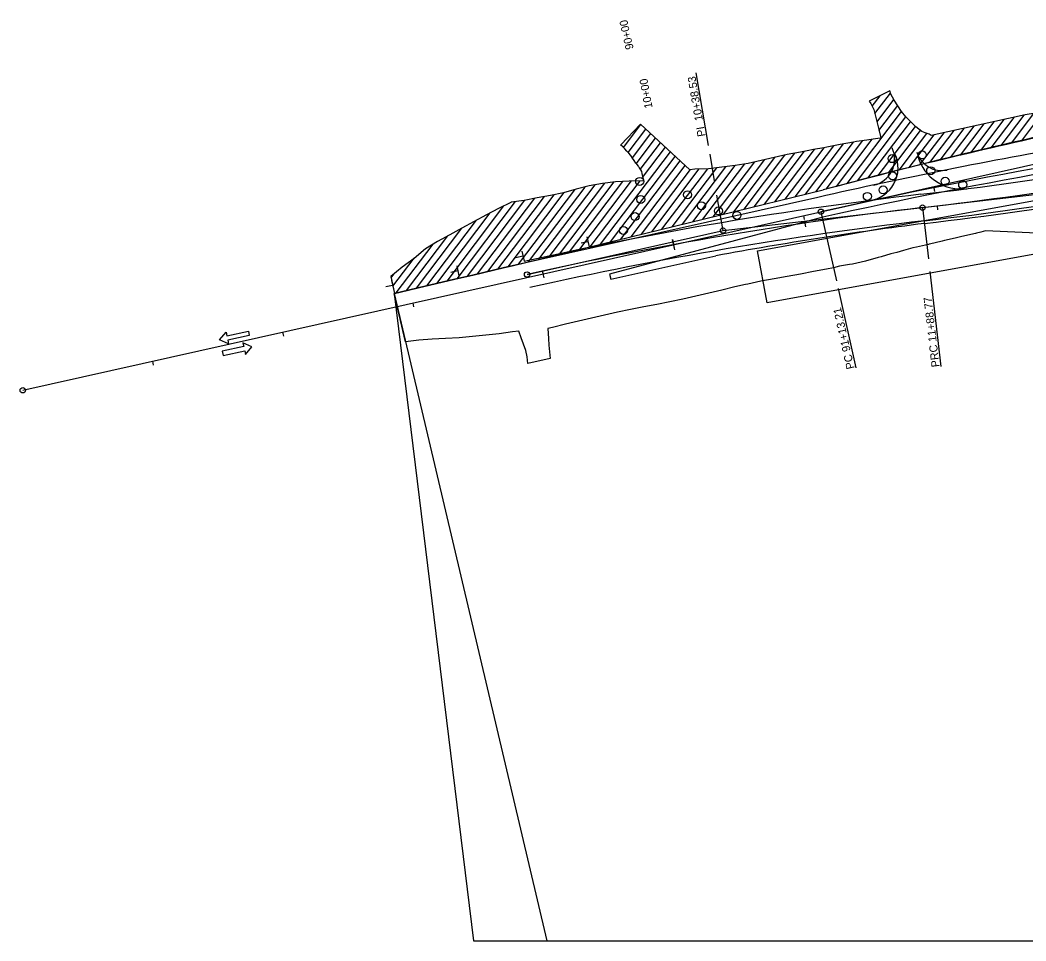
# Model space of a CAD drawing. Extents: x 1568809 to 1572786, y 728326 to 734907.
# Drawn here: x 1568809 to 1569563, y 731509 to 732199 of the extents above; entities that cross this region are included whole.
import ezdxf

# ---------------------------------------------------------------- set-up
doc = ezdxf.new("R2010")
doc.units = 0
for name, color, linetype in [('R_Horz Alg', 7, 'Continuous'), ('R_Horz Alg Annot', 7, 'Continuous'), ('R_MOT', 7, 'Continuous'), ('R_No Plot', 7, 'Continuous'), ('R_Proposed Road_Lane', 7, 'Continuous'), ('R_Striping', 7, 'Continuous')]:
    doc.layers.add(name, color=color, linetype=linetype)

msp = doc.modelspace()

# ---------------------------------------------------------------- linework, layer by layer
at = {"layer": 'R_Horz Alg'}
msp.add_line((1568810.94, 731921.74), (1569409.1, 732055.64), dxfattribs=at)
for centre, radius, start, end in [((1570243.51, 728328.17), 3819.72, 97.05, 102.61775), ((1569155.89, 734904.54), 2864.79, 276.60226, 282.33591), ((1569814.66, 729212.96), 2864.79, 96.60226, 102.61775)]:
    msp.add_arc(centre, radius, start, end, dxfattribs=at)
at = {"layer": 'R_Horz Alg Annot'}
for p, q in [((1569409.1, 732055.64), (1569590.36, 732096.21)), ((1569485.27, 732058.75), (1569627.78, 732075.25)), ((1569335.75, 732041.44), (1569485.27, 732058.75)), ((1569188.86, 732008.56), (1569335.75, 732041.44))]:
    msp.add_line(p, q, dxfattribs=at)
for points in [[(1569324.96, 732105.18), (1569315.71, 732159.76)], [(1569329.41, 732078.9), (1569326.05, 732098.72)], [(1569494.59, 732070.69), (1569494.01, 732073.63)], [(1569335.75, 732041.44), (1569331.22, 732068.17)], [(1569409.1, 732055.64), (1569420.68, 732003.92)], [(1569485.27, 732058.75), (1569489.73, 732020.26)], [(1569496.78, 732057.09), (1569496.42, 732060.06)], [(1569396.87, 732049.82), (1569396.21, 732052.75)], [(1569397.7, 732044.21), (1569397.26, 732047.18)], [(1569297.75, 732034.81), (1569299.5, 732027)], [(1569297.88, 732034.82), (1569299.32, 732026.95)], [(1569201.22, 732008.23), (1569200.57, 732011.16)], [(1569490.81, 732010.91), (1569499.07, 731939.55)], [(1569201.7, 732006.13), (1569201.04, 732009.06)], [(1569422, 731998.01), (1569435.32, 731938.54)], [(1569104.11, 731984.29), (1569103.46, 731987.22)], [(1569006.53, 731962.45), (1569005.87, 731965.37)], [(1568908.94, 731940.6), (1568908.29, 731943.53)]]:
    msp.add_lwpolyline(points, dxfattribs=at)
for centre in [(1569409.1, 732055.64), (1569485.27, 732058.75), (1569335.75, 732041.44), (1569188.86, 732008.56), (1568810.94, 731921.74)]:
    msp.add_circle(centre, 2, dxfattribs=at)
at = {"layer": 'R_MOT'}
for p, q in [((1569447.58, 732134.79), (1569453.47, 732142.57)), ((1569449.65, 732129.24), (1569461.27, 732144.61)), ((1569451.22, 732123.03), (1569463.86, 732139.74)), ((1569428.72, 732076.71), (1569469.57, 732130.71)), ((1569452.59, 732116.55), (1569466.71, 732135.21)), ((1569559.46, 732108.64), (1569575.93, 732130.41)), ((1569436.54, 732078.76), (1569472.84, 732126.75)), ((1569444.34, 732080.78), (1569476.37, 732123.13)), ((1569521.47, 732099.87), (1569539.02, 732123.06)), ((1569529.1, 732101.66), (1569546.53, 732124.71)), ((1569536.71, 732103.43), (1569554.04, 732126.35)), ((1569544.31, 732105.19), (1569561.56, 732127.99)), ((1569551.89, 732106.92), (1569568.76, 732129.23)), ((1569261.17, 732103.85), (1569274.18, 732121.06)), ((1569264.6, 732100.11), (1569277.87, 732117.64)), ((1569452.13, 732082.79), (1569479.9, 732119.51)), ((1569459.9, 732084.77), (1569483.84, 732116.42)), ((1569490.81, 732092.48), (1569508.97, 732116.49)), ((1569498.5, 732094.36), (1569516.48, 732118.14)), ((1569506.17, 732096.22), (1569524, 732119.78)), ((1569513.83, 732098.05), (1569531.51, 732121.42)), ((1569267.79, 732096.03), (1569281.55, 732114.23)), ((1569270.73, 732091.64), (1569285.24, 732110.81)), ((1569273.72, 732087.3), (1569288.93, 732107.4)), ((1569405.3, 732070.61), (1569433.5, 732107.89)), ((1569413.03, 732072.55), (1569440.6, 732108.98)), ((1569420.89, 732074.64), (1569447.6, 732109.95)), ((1569467.65, 732086.73), (1569488.53, 732114.33)), ((1569475.38, 732088.67), (1569493.95, 732113.21)), ((1569483.1, 732090.59), (1569501.46, 732114.85)), ((1569243.85, 732031.24), (1569296.3, 732100.56)), ((1569275.52, 732081.39), (1569292.61, 732103.98)), ((1569366.86, 732061.24), (1569396.94, 732101)), ((1569374.55, 732063.11), (1569404.21, 732102.32)), ((1569382.23, 732064.99), (1569411.47, 732103.63)), ((1569389.92, 732066.86), (1569418.8, 732105.04)), ((1569397.61, 732068.74), (1569426.16, 732106.48)), ((1569251.54, 732033.11), (1569299.98, 732097.15)), ((1569259.23, 732034.99), (1569303.67, 732093.73)), ((1569328.42, 732051.86), (1569359.52, 732092.98)), ((1569336.11, 732053.74), (1569367.08, 732094.69)), ((1569343.79, 732055.61), (1569374.6, 732096.33)), ((1569351.48, 732057.49), (1569382.17, 732098.06)), ((1569359.17, 732059.36), (1569389.6, 732099.58)), ((1569266.92, 732036.86), (1569307.35, 732090.32)), ((1569274.6, 732038.74), (1569311.27, 732087.21)), ((1569282.29, 732040.61), (1569317.91, 732087.7)), ((1569289.98, 732042.49), (1569324.29, 732087.84)), ((1569297.67, 732044.36), (1569331.05, 732088.49)), ((1569305.36, 732046.24), (1569337.96, 732089.34)), ((1569313.04, 732048.11), (1569344.92, 732090.25)), ((1569320.73, 732049.99), (1569352.09, 732091.43)), ((1569213.1, 732023.74), (1569254.11, 732077.94)), ((1569220.79, 732025.61), (1569260.72, 732078.4)), ((1569228.48, 732027.49), (1569267.22, 732078.7)), ((1569236.17, 732029.36), (1569273.61, 732078.86)), ((1569174.69, 732014.4), (1569216.78, 732070.04)), ((1569182.35, 732016.24), (1569224.62, 732072.12)), ((1569190.04, 732018.12), (1569232.44, 732074.17)), ((1569197.73, 732019.99), (1569239.95, 732075.8)), ((1569205.41, 732021.87), (1569247.16, 732077.05)), ((1569136.55, 732005.42), (1569180.25, 732063.18)), ((1569144.16, 732007.2), (1569187.31, 732064.23)), ((1569151.79, 732008.99), (1569194.69, 732065.7)), ((1569159.42, 732010.79), (1569201.94, 732067)), ((1569167.05, 732012.59), (1569209.27, 732068.39)), ((1569121.32, 732001.86), (1569161.28, 732054.68)), ((1569128.93, 732003.64), (1569171.57, 732060.01)), ((1569113.7, 732000.08), (1569150.88, 732049.23)), ((1569106.09, 731998.3), (1569140.1, 732043.26)), ((1569098.47, 731996.52), (1569129.53, 732037.58)), ((1569234.47, 732033.14), (1569229.37, 732032)), ((1569233.74, 732036.87), (1569235.42, 732029.41)), ((1569090.85, 731994.74), (1569118.55, 732031.35)), ((1569184.95, 732025.95), (1569186.62, 732018.49)), ((1569088.36, 731999.73), (1569104.26, 732020.75)), ((1569185.67, 732022.21), (1569180.58, 732021.07)), ((1569136.88, 732011.29), (1569131.79, 732010.15)), ((1569136.16, 732015.03), (1569137.83, 732007.56)), ((1569086.93, 732006.13), (1569089.16, 732009.08)), ((1569087.37, 732004.11), (1569089.04, 731996.64)), ((1569088.09, 732000.37), (1569082.99, 731999.23))]:
    msp.add_line(p, q, dxfattribs=at)
for points in [[(1568965.16, 731956.5), (1568958.49, 731959.66), (1568963.25, 731965.3), (1568963.84, 731962.55), (1568980.02, 731966.06), (1568980.73, 731962.77), (1568964.56, 731959.25)], [(1568977.84, 731948.59), (1568982.59, 731954.23), (1568975.93, 731957.39), (1568976.52, 731954.64), (1568960.35, 731951.12), (1568961.07, 731947.82), (1568977.24, 731951.34)]]:
    msp.add_lwpolyline(points, close=True, dxfattribs=at)
for centre in [(1569485.03, 732098.19), (1569462.43, 732095.42), (1569462.75, 732082.65), (1569491.39, 732086.39), (1569273.29, 732078.36), (1569502.21, 732078.47), (1569515.38, 732075.97), (1569309.21, 732068.34), (1569443.92, 732067.15), (1569455.75, 732071.97), (1569274.05, 732064.83), (1569319.59, 732060.08), (1569269.8, 732051.97), (1569332.27, 732056.21), (1569346.17, 732052.88), (1569261.13, 732041.56)]:
    msp.add_circle(centre, 3, dxfattribs=at)
at = {"layer": 'R_No Plot'}
for p, q in [((1569460.75, 732146.21), (1569445.41, 732138.55)), ((1569460.75, 732146.21), (1569445.41, 732138.55)), ((1569460.75, 732146.21), (1569445.41, 732138.55)), ((1569461.59, 732143.66), (1569460.75, 732146.21)), ((1569461.59, 732143.66), (1569460.75, 732146.21)), ((1569461.59, 732143.66), (1569460.75, 732146.21)), ((1569273.83, 732121.39), (1569259.04, 732105.9)), ((1569273.83, 732121.39), (1569259.04, 732105.9)), ((1569273.83, 732121.39), (1569259.04, 732105.9)), ((1569310.77, 732087.15), (1569273.83, 732121.39)), ((1569310.77, 732087.15), (1569273.83, 732121.39)), ((1569310.77, 732087.15), (1569273.83, 732121.39)), ((1569274.87, 732084.26), (1569276.05, 732079.04)), ((1569274.87, 732084.26), (1569276.05, 732079.04)), ((1569274.87, 732084.26), (1569276.05, 732079.04)), ((1569177.82, 732015.14), (1569410.85, 732071.97)), ((1569177.82, 732015.14), (1569410.85, 732071.97)), ((1569177.82, 732015.14), (1569410.85, 732071.97)), ((1569177.82, 732015.14), (1569410.85, 732071.97)), ((1569406.7, 732066.37), (1569177.82, 732015.14)), ((1569406.7, 732066.37), (1569177.82, 732015.14)), ((1569410.6, 732051.44), (1569250.71, 732008.91)), ((1569486.67, 732046.83), (1569486.65, 732046.83)), ((1569251.58, 732005), (1569330.38, 732022.64)), ((1569086.71, 732007.12), (1569089.55, 731994.43)), ((1569086.71, 732007.12), (1569089.55, 731994.43)), ((1569086.71, 732007.12), (1569089.55, 731994.43)), ((1569250.71, 732008.91), (1569251.58, 732005)), ((1569089.34, 731994.38), (1569203.67, 731508.95)), ((1569089.34, 731994.38), (1569148.82, 731508.95)), ((1569097.9, 731958.05), (1569089.34, 731994.38)), ((1569189.39, 731941.9), (1569189.02, 731946.74)), ((1569206.09, 731945.64), (1569189.39, 731941.9)), ((1569148.82, 731508.95), (1572786.15, 731508.95)), ((1569203.67, 731508.95), (1572786.15, 731508.95))]:
    msp.add_line(p, q, dxfattribs=at)
for points in [[(1569445.41, 732138.55), (1569446.62, 732136.69), (1569448.89, 732132.23)], [(1569445.41, 732138.55), (1569446.62, 732136.69), (1569448.89, 732132.23)], [(1569445.41, 732138.55), (1569446.62, 732136.69), (1569448.89, 732132.23)], [(1569491.86, 732112.75), (1569490.25, 732113.67), (1569487.33, 732114.8), (1569484.66, 732115.79), (1569480.18, 732119.22), (1569476.48, 732123.02), (1569472.79, 732126.81), (1569469.5, 732130.8), (1569466.8, 732135.06), (1569464.1, 732139.31), (1569461.59, 732143.66)], [(1569491.86, 732112.75), (1569490.25, 732113.67), (1569487.33, 732114.8), (1569484.66, 732115.79), (1569480.18, 732119.22), (1569476.48, 732123.02), (1569472.79, 732126.81), (1569469.5, 732130.8), (1569466.8, 732135.06), (1569464.1, 732139.31), (1569461.59, 732143.66)], [(1569491.86, 732112.75), (1569490.25, 732113.67), (1569487.33, 732114.8), (1569484.66, 732115.79), (1569480.18, 732119.22), (1569476.48, 732123.02), (1569472.79, 732126.81), (1569469.5, 732130.8), (1569466.8, 732135.06), (1569464.1, 732139.31), (1569461.59, 732143.66)], [(1569448.89, 732132.23), (1569450.15, 732127.31), (1569451.39, 732122.37), (1569452.41, 732117.33), (1569453.93, 732110.91)], [(1569448.89, 732132.23), (1569450.15, 732127.31), (1569451.39, 732122.37), (1569452.41, 732117.33), (1569453.93, 732110.91)], [(1569448.89, 732132.23), (1569450.15, 732127.31), (1569451.39, 732122.37), (1569452.41, 732117.33), (1569453.93, 732110.91)], [(1569609.76, 732130.47), (1569596.09, 732133.76), (1569562.31, 732128.16), (1569491.86, 732112.75)], [(1569609.76, 732130.47), (1569596.09, 732133.76), (1569562.31, 732128.16), (1569491.86, 732112.75)], [(1569609.76, 732130.47), (1569596.09, 732133.76), (1569562.31, 732128.16), (1569491.86, 732112.75)], [(1569453.93, 732110.91), (1569453.55, 732110.81), (1569448.24, 732110.04), (1569443.51, 732109.39), (1569435.8, 732108.31), (1569433.48, 732107.89), (1569423.54, 732105.98), (1569423.5, 732105.97), (1569413.61, 732104.01), (1569411.2, 732103.58), (1569403.64, 732102.22), (1569398.87, 732101.35), (1569393.74, 732100.41), (1569383.93, 732098.46), (1569374.18, 732096.24), (1569364.41, 732094.1), (1569354.67, 732091.86), (1569344.78, 732090.22), (1569334.83, 732088.93), (1569332.94, 732088.68), (1569324.82, 732087.85), (1569314.62, 732087.62), (1569310.77, 732087.15)], [(1569453.93, 732110.91), (1569453.55, 732110.81), (1569448.24, 732110.04), (1569443.51, 732109.39), (1569435.8, 732108.31), (1569433.48, 732107.89), (1569423.54, 732105.98), (1569423.5, 732105.97), (1569413.61, 732104.01), (1569411.2, 732103.58), (1569403.64, 732102.22), (1569398.87, 732101.35), (1569393.74, 732100.41), (1569383.93, 732098.46), (1569374.18, 732096.24), (1569364.41, 732094.1), (1569354.67, 732091.86), (1569344.78, 732090.22), (1569334.83, 732088.93), (1569332.94, 732088.68), (1569324.82, 732087.85), (1569314.62, 732087.62), (1569310.77, 732087.15)], [(1569453.93, 732110.91), (1569453.55, 732110.81), (1569448.24, 732110.04), (1569443.51, 732109.39), (1569435.8, 732108.31), (1569433.48, 732107.89), (1569423.54, 732105.98), (1569423.5, 732105.97), (1569413.61, 732104.01), (1569411.2, 732103.58), (1569403.64, 732102.22), (1569398.87, 732101.35), (1569393.74, 732100.41), (1569383.93, 732098.46), (1569374.18, 732096.24), (1569364.41, 732094.1), (1569354.67, 732091.86), (1569344.78, 732090.22), (1569334.83, 732088.93), (1569332.94, 732088.68), (1569324.82, 732087.85), (1569314.62, 732087.62), (1569310.77, 732087.15)], [(1569270.37, 732092.14), (1569271.26, 732090.93), (1569272.13, 732089.68), (1569272.3, 732089.44), (1569272.99, 732088.42), (1569273.83, 732087.14), (1569274.53, 732085.78)], [(1569270.37, 732092.14), (1569271.26, 732090.93), (1569272.13, 732089.68), (1569272.3, 732089.44), (1569272.99, 732088.42), (1569273.83, 732087.14), (1569274.53, 732085.78)], [(1569270.37, 732092.14), (1569271.26, 732090.93), (1569272.13, 732089.68), (1569272.3, 732089.44), (1569272.99, 732088.42), (1569273.83, 732087.14), (1569274.53, 732085.78)], [(1569274.53, 732085.78), (1569274.54, 732085.74), (1569274.87, 732084.26)], [(1569274.53, 732085.78), (1569274.54, 732085.74), (1569274.87, 732084.26)], [(1569274.53, 732085.78), (1569274.54, 732085.74), (1569274.87, 732084.26)], [(1569276.05, 732079.04), (1569275.59, 732078.9), (1569265.39, 732078.66), (1569255.27, 732078.09), (1569245.31, 732076.82), (1569235.48, 732074.96), (1569225.8, 732072.43), (1569216.12, 732069.87), (1569206.35, 732067.77), (1569196.48, 732066.06), (1569186.67, 732064.1), (1569176.95, 732062.71), (1569176.75, 732062.67)], [(1569276.05, 732079.04), (1569275.59, 732078.9), (1569265.39, 732078.66), (1569255.27, 732078.09), (1569245.31, 732076.82), (1569235.48, 732074.96), (1569225.8, 732072.43), (1569216.12, 732069.87), (1569206.35, 732067.77), (1569196.48, 732066.06), (1569186.67, 732064.1), (1569176.95, 732062.71), (1569176.75, 732062.67)], [(1569276.05, 732079.04), (1569275.59, 732078.9), (1569265.39, 732078.66), (1569255.27, 732078.09), (1569245.31, 732076.82), (1569235.48, 732074.96), (1569225.8, 732072.43), (1569216.12, 732069.87), (1569206.35, 732067.77), (1569196.48, 732066.06), (1569186.67, 732064.1), (1569176.95, 732062.71), (1569176.75, 732062.67)], [(1569176.75, 732062.67), (1569167.56, 732057.94), (1569158.37, 732053.18), (1569149.21, 732048.35), (1569140.1, 732043.26), (1569130.95, 732038.36), (1569121.82, 732033.36), (1569112.81, 732027.83), (1569104.17, 732020.67), (1569095.4, 732014.06), (1569086.71, 732007.12)], [(1569176.75, 732062.67), (1569167.56, 732057.94), (1569158.37, 732053.18), (1569149.21, 732048.35), (1569140.1, 732043.26), (1569130.95, 732038.36), (1569121.82, 732033.36), (1569112.81, 732027.83), (1569104.17, 732020.67), (1569095.4, 732014.06), (1569086.71, 732007.12)], [(1569176.75, 732062.67), (1569167.56, 732057.94), (1569158.37, 732053.18), (1569149.21, 732048.35), (1569140.1, 732043.26), (1569130.95, 732038.36), (1569121.82, 732033.36), (1569112.81, 732027.83), (1569104.17, 732020.67), (1569095.4, 732014.06), (1569086.71, 732007.12)], [(1569692.82, 732047.58), (1569649.72, 732050.12), (1569611.57, 732041.99), (1569590.97, 732040.46), (1569570.96, 732039.46), (1569532.47, 732041.3)], [(1569532.47, 732041.3), (1569528.91, 732040.43), (1569525.62, 732039.54), (1569525, 732039.4), (1569519.28, 732038.12), (1569513.68, 732036.78), (1569509.65, 732035.8), (1569501.75, 732034.01), (1569500, 732033.6), (1569490.57, 732031.34), (1569490.37, 732031.29), (1569489.84, 732031.17), (1569480.72, 732029.12), (1569477.89, 732028.48), (1569471.12, 732026.67), (1569466.08, 732025.16), (1569461.56, 732024.07), (1569454.27, 732021.91), (1569452.06, 732021.2), (1569442.54, 732018.45), (1569442.5, 732018.44), (1569432.87, 732016.41), (1569430.51, 732016.02), (1569423.12, 732014.72), (1569418.52, 732013.56), (1569413.41, 732012.54), (1569403.56, 732010.76), (1569393.72, 732008.94), (1569383.88, 732007.15), (1569374.03, 732005.34), (1569364.19, 732003.53), (1569354.43, 732001.36), (1569352.56, 732001.02), (1569344.64, 731999.32), (1569334.95, 731996.81), (1569325.2, 731994.59), (1569315.46, 731992.32), (1569305.73, 731990.03), (1569295.91, 731988.1), (1569286.1, 731986.17), (1569276.28, 731984.24), (1569266.48, 731982.24), (1569256.68, 731980.24), (1569246.92, 731978.07), (1569237.18, 731975.79), (1569227.44, 731973.53), (1569217.7, 731971.28), (1569207.99, 731968.88), (1569204.43, 731968.1)], [(1569177.82, 732015.14), (1569172.01, 732013.76), (1569148.27, 732008.16), (1569134.64, 732004.97), (1569121.01, 732001.79), (1569107.37, 731998.6), (1569093.74, 731995.42), (1569089.34, 731994.38)], [(1569177.82, 732015.14), (1569172.01, 732013.76), (1569148.27, 732008.16), (1569134.64, 732004.97), (1569121.01, 732001.79), (1569107.37, 731998.6), (1569093.74, 731995.42), (1569089.34, 731994.38)], [(1569089.34, 731994.38), (1569093.74, 731995.42), (1569107.37, 731998.6), (1569121.01, 732001.79), (1569134.64, 732004.97), (1569148.27, 732008.16), (1569172.01, 732013.76), (1569177.82, 732015.14)], [(1569089.55, 731994.43), (1569093.74, 731995.42), (1569107.37, 731998.6), (1569121.01, 732001.79), (1569134.64, 732004.97), (1569148.27, 732008.16), (1569172.01, 732013.76), (1569177.82, 732015.14)], [(1569089.55, 731994.43), (1569093.74, 731995.42), (1569107.37, 731998.6), (1569121.01, 732001.79), (1569134.64, 732004.97), (1569148.27, 732008.16), (1569172.01, 732013.76), (1569177.82, 732015.14)], [(1569089.55, 731994.43), (1569093.74, 731995.42), (1569107.37, 731998.6), (1569121.01, 732001.79), (1569134.64, 732004.97), (1569148.27, 732008.16), (1569172.01, 732013.76), (1569177.82, 732015.14)], [(1569182.8, 731966.06), (1569177.97, 731965.66), (1569168.05, 731964.19), (1569158.06, 731963.01), (1569148.05, 731961.96), (1569138.01, 731961.03), (1569127.87, 731960.54), (1569117.75, 731959.97), (1569107.66, 731959.27), (1569097.9, 731958.05)], [(1569189.02, 731946.74), (1569187.92, 731951.62), (1569186.18, 731956.35), (1569184.45, 731961.09), (1569182.8, 731966.06)], [(1569204.43, 731968.1), (1569204.91, 731960.54), (1569205.25, 731955.5), (1569205.67, 731950.47), (1569206.09, 731945.64)]]:
    msp.add_lwpolyline(points, dxfattribs=at)
msp.add_lwpolyline([(1569361.7, 732026.33), (1569753.23, 732097.58), (1569760.32, 732058.65), (1569368.79, 731987.39)], close=True, dxfattribs=at)
for centre, radius, start, end in [((1570398.03, 728391.24), 3810.81, 102.04699, 105.01357), ((1570398.03, 728391.24), 3810.81, 102.04699, 105.01357), ((1570398.03, 728391.24), 3810.81, 102.04699, 105.01357), ((1570380.82, 728500.81), 3700.54, 102.22905, 105.19563), ((1570242.6, 728334.71), 3808.72, 97.05, 102.61775), ((1569215.77, 732058.74), 64, 31.4584, 47.47011), ((1569215.77, 732058.74), 64, 31.4584, 47.47011), ((1569215.77, 732058.74), 64, 31.4584, 47.47011), ((1570255.23, 728328.47), 3833, 99.82313, 102.78971), ((1570255.23, 728328.47), 3833, 99.82313, 102.78971), ((1569442.12, 732088.53), 24.81, 277.3817, 24.95394), ((1569514.32, 732106.35), 33.74, 195.56509, 277.29942), ((1569155.89, 734904.54), 2876.79, 276.60226, 282.33592), ((1569844.49, 729218.01), 2851.36, 97.20901, 100.38744)]:
    msp.add_arc(centre, radius, start, end, dxfattribs=at)
at = {"layer": 'R_Proposed Road_Lane'}
for centre, start, end in [((1569444.38, 732095.05), 281.97737, 24.95394), ((1569499.96, 732106.42), 197.74389, 281.13327)]:
    msp.add_arc(centre, 20, start, end, dxfattribs=at)
at = {"layer": 'R_Striping'}
for centre, radius, start, end in [((1569155.89, 734904.54), 2854.79, 276.60226, 282.33591), ((1569155.89, 734904.54), 2854.79, 276.60226, 282.33591), ((1569155.89, 734904.54), 2864.79, 276.60226, 282.33591), ((1569155.89, 734904.54), 2874.79, 276.60226, 282.33591), ((1569814.66, 729212.96), 2874.79, 96.60226, 102.61775), ((1569814.66, 729212.96), 2874.79, 96.60226, 102.61775), ((1569814.66, 729212.96), 2864.79, 96.60226, 102.61775), ((1569814.66, 729212.96), 2854.79, 96.60226, 102.61775)]:
    msp.add_arc(centre, radius, start, end, dxfattribs=at)

# ---------------------------------------------------------------- texts
at = {"layer": 'R_Horz Alg Annot'}
for s, rotation, p in [('90+00', 102.61775, (1569268.79, 732177.94)), ('10+00', 100.37775, (1569283, 732133.69)), ('PI  10+38.53', 99.61001, (1569322.71, 732112.45)), ('PRC 11+88.77', 96.60226, (1569498.08, 731939.43)), ('PC 91+13.21', 102.61775, (1569434.34, 731938.32))]:
    msp.add_text(s, height=6, rotation=rotation, dxfattribs=at).set_placement(p)

doc.saveas('drawing.dxf')
